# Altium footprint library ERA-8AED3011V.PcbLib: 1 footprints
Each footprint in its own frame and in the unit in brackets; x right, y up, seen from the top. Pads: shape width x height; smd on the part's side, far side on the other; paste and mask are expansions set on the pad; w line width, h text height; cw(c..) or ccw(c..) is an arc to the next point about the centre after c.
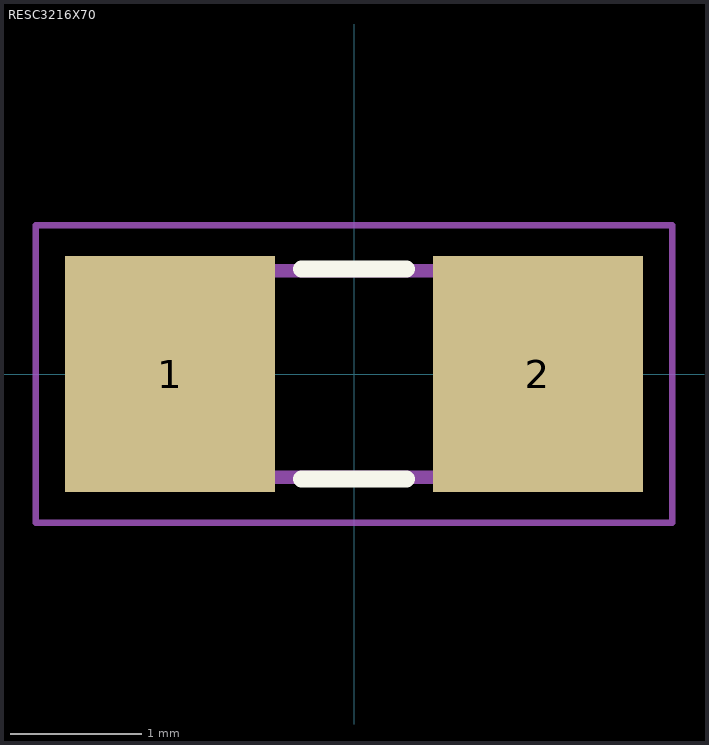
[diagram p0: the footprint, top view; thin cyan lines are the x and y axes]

## RESC3216X70 [mm]
pads (2):
  rect 1.6x1.8 smd: 1(-1.4,0) 2(1.4,0)
Top Overlay:
  lines w0.127: -0.4,-0.8 0.4,-0.8 ; -0.4,0.8 0.4,0.8
Mechanical 4:
  lines w0.102: -0.965,-0.787 0.965,-0.787 -0.965,-0.787 ; -0.965,0.787 0.965,0.787 -0.965,0.787
Mechanical 16:
  lines w0.051: -2.423,-1.133 -2.423,1.133 2.423,1.133 2.423,-1.133 -2.423,-1.133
